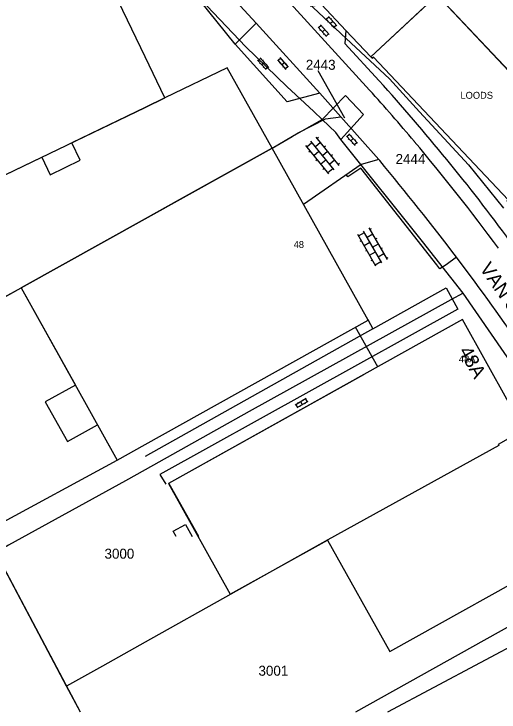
# Model space of a CAD drawing. Extents: x 148816 to 151297, y 399515 to 402500.
# Drawn here: x 149976.4 to 150063.7, y 399515.3 to 399641 of the extents above; entities that cross this region are included whole.
import ezdxf

# ---------------------------------------------------------------- set-up
doc = ezdxf.new("R2010")
doc.units = 0
for name, color, linetype in [('B01 Hoofdgebouw  [D] Norm', 7, 'Continuous'), ('B01 Hoofdgebouw  [T] Norm', 7, 'Continuous'), ('B01 hoofgebouw', 7, 'Continuous'), ('B02 Bijgebouw  [T] Norm', 7, 'Continuous'), ('G01 perceelsgrens', 7, 'Continuous'), ('S02 Open verharding  Norm', 7, 'Continuous'), ('T04 Haag heg  [D] Gem', 7, 'Continuous'), ('V00 Kant verharding algemeen  [T] Norm', 7, 'Continuous'), ('V00 Kant verharding algemeen secundair  [T] Gem', 7, 'Continuous'), ('Z01 perceelnummer', 7, 'Continuous'), ('Z02 huisnummer', 7, 'Continuous'), ('Z02 Huisnummer  [Tekst] Norm', 7, 'Continuous'), ('Z06 straatnaam', 7, 'Continuous')]:
    doc.layers.add(name, color=color, linetype=linetype)

msp = doc.modelspace()

# ---------------------------------------------------------------- linework, layer by layer
at = {"layer": 'B01 Hoofdgebouw  [D] Norm'}
msp.add_lwpolyline([(150009.64, 399546.87), (150004.28, 399556.5), (150039.35, 399576.04)], dxfattribs=at)
at = {"layer": 'B01 Hoofdgebouw  [T] Norm'}
for p, q in [((150000, 399633.28), (149995.2, 399643.26)), ((150052.55, 399644.45), (150040.65, 399633.25)), ((150079.4, 399615.95), (150052.55, 399644.45)), ((150003.56, 399625.87), (150000, 399633.28)), ((150040.65, 399633.25), (150040.88, 399633.01)), ((150040.88, 399633.01), (150041.1, 399633.21)), ((150041.1, 399633.21), (150065.32, 399607.52)), ((150000, 399624.16), (150003.56, 399625.87)), ((149954.92, 399602.46), (150000, 399624.16)), ((150022.83, 399616.84), (150000, 399604.1)), ((150040.14, 399585.85), (150022.83, 399616.84)), ((150000, 399604.1), (149977.69, 399591.64)), ((149977.69, 399591.64), (149994.98, 399560.65)), ((150000, 399563.45), (150040.14, 399585.85)), ((150057.1, 399585.95), (150039.35, 399576.04)), ((149994.98, 399560.65), (150000, 399563.45))]:
    msp.add_line(p, q, dxfattribs=at)
for points in [[(149981.38, 399615.2), (149982.89, 399612.04), (149988.3, 399614.64), (149986.78, 399617.8)], [(150074.62, 399546.87), (150077.85, 399548.74), (150057.1, 399585.95)], [(149987.44, 399574.17), (149982.02, 399571.15), (149986.02, 399563.99), (149991.43, 399567.01)]]:
    msp.add_lwpolyline(points, dxfattribs=at)
at = {"layer": 'B01 hoofgebouw'}
for points in [[(150000, 399633.28), (149995.2, 399643.26), (149997.27, 399644.26), (149995.21, 399648.55), (149994.05, 399647.99), (149988.81, 399658.84), (149987.92, 399658.41), (149981.89, 399670.95), (149973.96, 399667.15), (149971.76, 399671.74), (149972.04, 399671.88), (149956.4, 399704.35), (149934.6, 399693.85), (149930.29, 399702.78), (149925.79, 399700.61)], [(150065.33, 399607.09), (150065.11, 399607.32), (150065.32, 399607.52), (150041.1, 399633.21), (150040.88, 399633.01), (150040.65, 399633.25), (150052.55, 399644.45), (150079.4, 399615.95), (150072.4, 399609.35), (150070.2, 399611.68), (150065.33, 399607.09)], [(150003.56, 399625.87), (150000, 399633.28)], [(150003.56, 399625.87), (150000, 399624.16)], [(150000, 399624.16), (149986.78, 399617.8)], [(149981.38, 399615.2), (149982.89, 399612.04), (149988.3, 399614.64), (149986.78, 399617.8)], [(150000, 399563.45), (150040.14, 399585.85), (150022.83, 399616.84), (150006.11, 399607.51), (150000, 399604.1)], [(149954.92, 399602.46), (149981.38, 399615.2)], [(150000, 399604.1), (149977.69, 399591.64)], [(149977.69, 399591.64), (149987.44, 399574.17)], [(150077.86, 399548.74), (150057.1, 399585.95), (150039.35, 399576.04)], [(150039.35, 399576.04), (150004.19, 399556.42), (150015.32, 399536.48), (150032.83, 399546.25), (150044.04, 399526.17), (150075.06, 399543.49)], [(149987.44, 399574.17), (149982.02, 399571.15), (149986.02, 399563.99), (149991.43, 399567.01)], [(149991.43, 399567.01), (149994.98, 399560.65)], [(149994.98, 399560.65), (150000, 399563.45)], [(149988.36, 399515.27), (149973.39, 399543.37)], [(150068.62, 399528.6), (150043.61, 399515.27)]]:
    msp.add_lwpolyline(points, dxfattribs=at)
at = {"layer": 'B02 Bijgebouw  [T] Norm'}
for points in [[(150005.05, 399547.82), (150007.23, 399549.04), (150008.44, 399546.87)], [(150005.58, 399546.87), (150005.05, 399547.82)]]:
    msp.add_lwpolyline(points, dxfattribs=at)
at = {"layer": 'G01 perceelsgrens'}
for points in [[(150000, 399677.56), (150004.45, 399671.61), (150008.5, 399666.18), (150011.96, 399661.79), (150017.85, 399655.08), (150026.24, 399645.99), (150036.16, 399636.57), (150043.99, 399629.34), (150049.36, 399623.39), (150058.2, 399613.83), (150064.49, 399606)], [(150030.39, 399623.4), (150025.5, 399627.94), (150018.13, 399635.07), (150011.09, 399642.46), (150005.49, 399648.73), (150000, 399655.41)], [(150031.89, 399622.01), (150036.04, 399626.28), (150039.28, 399622.9), (150035.24, 399618.4)], [(150031.89, 399622.01), (150030.39, 399623.4)], [(150026.47, 399618.92), (150031.89, 399622.01)], [(150034.32, 399619.62), (150031.89, 399622.01)], [(150035.24, 399618.4), (150034.32, 399619.62)], [(150000, 399604.1), (150022.83, 399616.84), (150026.47, 399618.92)], [(150057.27, 399590.73), (150049.95, 399600.03), (150035.24, 399618.4)], [(149951.4, 399577.02), (149977.69, 399591.64), (150000, 399604.1)], [(150057.27, 399590.73), (150055.01, 399589.48)], [(150072.56, 399568.54), (150057.27, 399590.73)], [(150055.01, 399589.48), (150018.74, 399569.42), (150000, 399558.92)], [(150072.56, 399568.54), (150063.57, 399563.48), (150063.65, 399563.28), (150032.9, 399546.26), (150015.42, 399536.51), (150000, 399527.88)], [(150000, 399558.92), (149996.47, 399556.94), (149975.4, 399545.31), (149973.05, 399544)], [(149985.86, 399519.96), (149973.05, 399544)], [(150087.18, 399542.81), (150037.84, 399515.27)], [(150000, 399527.88), (149992.29, 399523.56)], [(149992.29, 399523.56), (149985.86, 399519.96)], [(149988.36, 399515.27), (149985.86, 399519.96)]]:
    msp.add_lwpolyline(points, dxfattribs=at)
at = {"layer": 'S02 Open verharding  Norm'}
for p, q in [((150034.08, 399638.44), (150032.54, 399640.14)), ((150033.09, 399640.43), (150032.64, 399640.03)), ((150032.87, 399639.56), (150032.98, 399639.66)), ((150034.53, 399638.84), (150032.99, 399640.54)), ((150033.31, 399639.29), (150033.76, 399639.69)), ((150033.42, 399640.06), (150033.53, 399640.16)), ((150032.67, 399636.91), (150031.13, 399638.62)), ((150031.67, 399638.91), (150031.23, 399638.51)), ((150033.11, 399637.31), (150031.57, 399639.02)), ((150032.01, 399638.54), (150032.12, 399638.64)), ((150033.54, 399638.82), (150033.65, 399638.92)), ((150034.43, 399638.95), (150033.98, 399638.55)), ((150034.09, 399639.32), (150034.2, 399639.42)), ((150031.45, 399638.03), (150031.56, 399638.13)), ((150031.9, 399637.76), (150032.34, 399638.17)), ((150032.12, 399637.29), (150032.23, 399637.39)), ((150033.01, 399637.42), (150032.57, 399637.02)), ((150032.68, 399637.8), (150032.79, 399637.9)), ((150020.24, 399632.68), (150021.79, 399630.97)), ((150020.34, 399632.56), (150020.78, 399632.97)), ((150020.68, 399632.2), (150020.56, 399632.09)), ((150020.68, 399633.08), (150022.23, 399631.38)), ((150021.46, 399632.23), (150021.01, 399631.83)), ((150021.23, 399632.7), (150021.12, 399632.6)), ((150021.9, 399631.96), (150021.79, 399631.86)), ((150025.35, 399631.01), (150023.85, 399632.76)), ((150024.4, 399633.04), (150023.95, 399632.64)), ((150024.16, 399632.17), (150024.27, 399632.27)), ((150025.8, 399631.41), (150024.3, 399633.15)), ((150024.6, 399631.89), (150025.05, 399632.28)), ((150024.73, 399632.66), (150024.84, 399632.75)), ((150025.38, 399631.9), (150025.49, 399632)), ((150021.35, 399631.46), (150021.24, 399631.35)), ((150021.68, 399631.09), (150022.13, 399631.49)), ((150024.81, 399631.41), (150024.92, 399631.51)), ((150025.71, 399631.52), (150025.25, 399631.13)), ((150038.25, 399617.73), (150036.66, 399619.39)), ((150034.93, 399613.71), (150030.76, 399618.83)), ((150030.95, 399618.6), (150031.18, 399618.79)), ((150037.81, 399617.31), (150036.23, 399618.98)), ((150036.77, 399619.29), (150036.33, 399618.87)), ((150036.57, 399618.41), (150036.68, 399618.51)), ((150037.02, 399618.15), (150037.45, 399618.56)), ((150037.11, 399618.92), (150037.22, 399619.03)), ((150037.8, 399618.2), (150037.91, 399618.3)), ((150033.07, 399612.19), (150028.9, 399617.32)), ((150029.09, 399617.08), (150030.02, 399617.84)), ((150034, 399612.95), (150029.83, 399618.07)), ((150031.58, 399617.82), (150030.65, 399617.06)), ((150032.21, 399617.04), (150032.45, 399617.23)), ((150037.26, 399617.68), (150037.36, 399617.78)), ((150038.14, 399617.84), (150037.71, 399617.42)), ((150029.72, 399616.31), (150029.49, 399616.12)), ((150030.35, 399615.53), (150031.28, 399616.29)), ((150031.91, 399615.51), (150032.85, 399616.27)), ((150033.48, 399615.49), (150033.71, 399615.68)), ((150030.98, 399614.75), (150030.75, 399614.57)), ((150031.61, 399613.98), (150032.55, 399614.73)), ((150033.18, 399613.96), (150034.11, 399614.72)), ((150032.24, 399613.2), (150032.01, 399613.01)), ((150032.88, 399612.43), (150033.81, 399613.18)), ((150034.74, 399613.94), (150034.97, 399614.13)), ((150042.59, 399596.15), (150039.31, 399601.88)), ((150043.63, 399596.75), (150040.35, 399602.47)), ((150040.5, 399602.21), (150040.76, 399602.36)), ((150041.55, 399595.55), (150038.27, 399601.28)), ((150038.42, 399601.02), (150039.46, 399601.62)), ((150040.99, 399601.35), (150039.95, 399600.75)), ((150041.49, 399600.48), (150041.75, 399600.63)), ((150038.91, 399600.15), (150038.65, 399600)), ((150039.41, 399599.28), (150040.45, 399599.88)), ((150040.95, 399599.01), (150041.99, 399599.61)), ((150039.91, 399598.42), (150039.65, 399598.27)), ((150040.4, 399597.55), (150041.45, 399598.15)), ((150042.49, 399598.74), (150042.75, 399598.89)), ((150041.94, 399597.28), (150042.98, 399597.87)), ((150043.48, 399597.01), (150043.74, 399597.16)), ((150040.9, 399596.68), (150040.64, 399596.53)), ((150041.4, 399595.81), (150042.44, 399596.41)), ((150028.99, 399571.71), (150027, 399570.55)), ((150028.86, 399571.64), (150029.16, 399571.12)), ((150027.13, 399570.63), (150027.43, 399570.11)), ((150029.29, 399571.19), (150027.3, 399570.04)), ((150027.56, 399570.88), (150027.49, 399571.01)), ((150027.94, 399570.23), (150027.87, 399570.36)), ((150028.3, 399570.61), (150028, 399571.13)), ((150028.43, 399571.38), (150028.35, 399571.51)), ((150028.81, 399570.74), (150028.73, 399570.87))]:
    msp.add_line(p, q, dxfattribs=at)
at = {"layer": 'T04 Haag heg  [D] Gem'}
msp.add_line((150041.86, 399577.44), (150037.87, 399584.58), dxfattribs=at)
msp.add_lwpolyline([(150022.83, 399616.84), (150014.77, 399631.27), (150003.56, 399625.87)], dxfattribs=at)
at = {"layer": 'V00 Kant verharding algemeen  [T] Norm'}
for p, q in [((150016.19, 399635.55), (150009.71, 399643.68)), ((150040.65, 399633.25), (150036.14, 399638.01))]:
    msp.add_line(p, q, dxfattribs=at)
for points in [[(150012.22, 399661.88), (150029.85, 399642.4), (150031.77, 399642.69), (150036.14, 399638.01), (150035.96, 399635.68), (150042.1, 399628.95)], [(150010.11, 399660.61), (150015.58, 399654.5), (150040.38, 399627.27)], [(150020, 399639.31), (150014.2, 399645.64)], [(150031.42, 399626.73), (150025.58, 399625.14), (150016.19, 399635.55), (150020, 399639.31)], [(150031.42, 399626.73), (150020, 399639.31)], [(150035.24, 399622.45), (150031.42, 399626.73)], [(150027.55, 399619.56), (150032.49, 399622.1)], [(150032.49, 399622.1), (150035.24, 399622.45)], [(150042.05, 399614.78), (150035.24, 399622.45)], [(150022.83, 399616.84), (150027.55, 399619.56)], [(150042.05, 399614.78), (150038.91, 399613.86), (150028.5, 399606.7)], [(150042.22, 399614.59), (150042.05, 399614.78)], [(150056.04, 399597.19), (150054.21, 399595.8), (150053.04, 399595.12), (150052.49, 399595.82), (150038.85, 399613.22), (150036.49, 399611.68), (150036.23, 399612.01)], [(150059.39, 399592.7), (150056.04, 399597.19)], [(149967.72, 399558.14), (149955.59, 399579.56), (149977.69, 399591.64)], [(150040.14, 399585.85), (150041.01, 399584.31), (150000, 399561.29)], [(150040.08, 399585.97), (150041.01, 399584.31)], [(149972.98, 399548.74), (149994.98, 399560.65)]]:
    msp.add_lwpolyline(points, dxfattribs=at)
for centre, radius, start, end in [((149771.31, 399383.59), 365.42, 36.323, 42.18), ((149809.36, 399417.02), 312.37, 40.0548, 42.3056), ((149754.39, 399371.15), 383.96, 36.3618, 40.0154), ((149660.42, 399296.98), 496.63, 37.1924, 39.7565), ((149708.46, 399333.9), 436.03, 31.0026, 36.4076)]:
    msp.add_arc(centre, radius, start, end, dxfattribs=at)
at = {"layer": 'V00 Kant verharding algemeen secundair  [T] Gem'}
for points in [[(150041.01, 399584.31), (150054.19, 399591.68), (150056.27, 399587.81)], [(150056.27, 399587.81), (150002.63, 399558.04), (150003.72, 399556.29)]]:
    msp.add_lwpolyline(points, dxfattribs=at)
at = {"layer": 'Z01 perceelnummer'}
msp.add_lwpolyline([(150031.06, 399630.84), (150035.9, 399622.27)], dxfattribs=at)

# ---------------------------------------------------------------- texts
for s, p in [('2443', (150028.92, 399630.94)), ('2444', (150045.08, 399613.97)), ('3000', (149992.68, 399542.89)), ('3001', (150020.4, 399521.81))]:
    msp.add_text(s, height=1.8, dxfattribs=at).set_placement(p)
at = {"layer": 'Z02 huisnummer'}
msp.add_text('48A', height=2.5, rotation=299.1548, dxfattribs=at).set_placement((150056.39, 399580.29))
at = {"layer": 'Z02 Huisnummer  [Tekst] Norm'}
for s, p in [('LOODS', (150056.76, 399625.72)), ('48', (150026.73, 399598.84)), ('48A', (150056.48, 399578.23))]:
    msp.add_text(s, height=1.25, dxfattribs=at).set_placement(p)
at = {"layer": 'Z06 straatnaam'}
msp.add_text('VAN SALMSTRAAT', height=2.5, rotation=304.6915, dxfattribs=at).set_placement((150060.12, 399595.17))

doc.saveas('drawing.dxf')
